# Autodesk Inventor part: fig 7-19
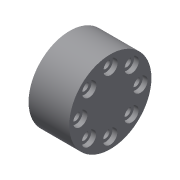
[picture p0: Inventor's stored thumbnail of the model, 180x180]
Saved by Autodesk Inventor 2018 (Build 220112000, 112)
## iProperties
Created: 2004-05
Part Number: fig 7-19
Document SubType Name: Modeling
Designer: CADCIM Technologies
Manufacturer: Standard
Standards Organization: Custom
Density: 1 g/cm^3
Material: Generic
Appearance: Default
Author: CADCIM Technologies
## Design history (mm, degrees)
sketch "Sketch1"
  geometry: C1 r 17.175 at (0, 0)
  constraints: 1 centre point
extrude "Extrusion1" new body sketch "Sketch1" distance "d0" = 17; taper "d1" = 0 deg
sketch "Sketch2"
  geometry: 1 further point
hole "Hole1" sketch "Sketch2" at (12.571, -0.074) diameter "d2" = 3.5; stored, may be unused: countersink angle "d6" = 90 deg, drill point angle "d8" = 118 deg; dims "d3" = 6, "d4" = 6, "d5" = 2, "d7" = 8
pattern_circular "Circular Pattern1" dims angle "d11" = 360 deg
body "Solid1"
